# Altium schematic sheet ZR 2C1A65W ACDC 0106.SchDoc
size A3; SheetNumber: 2; SheetTotal: 2
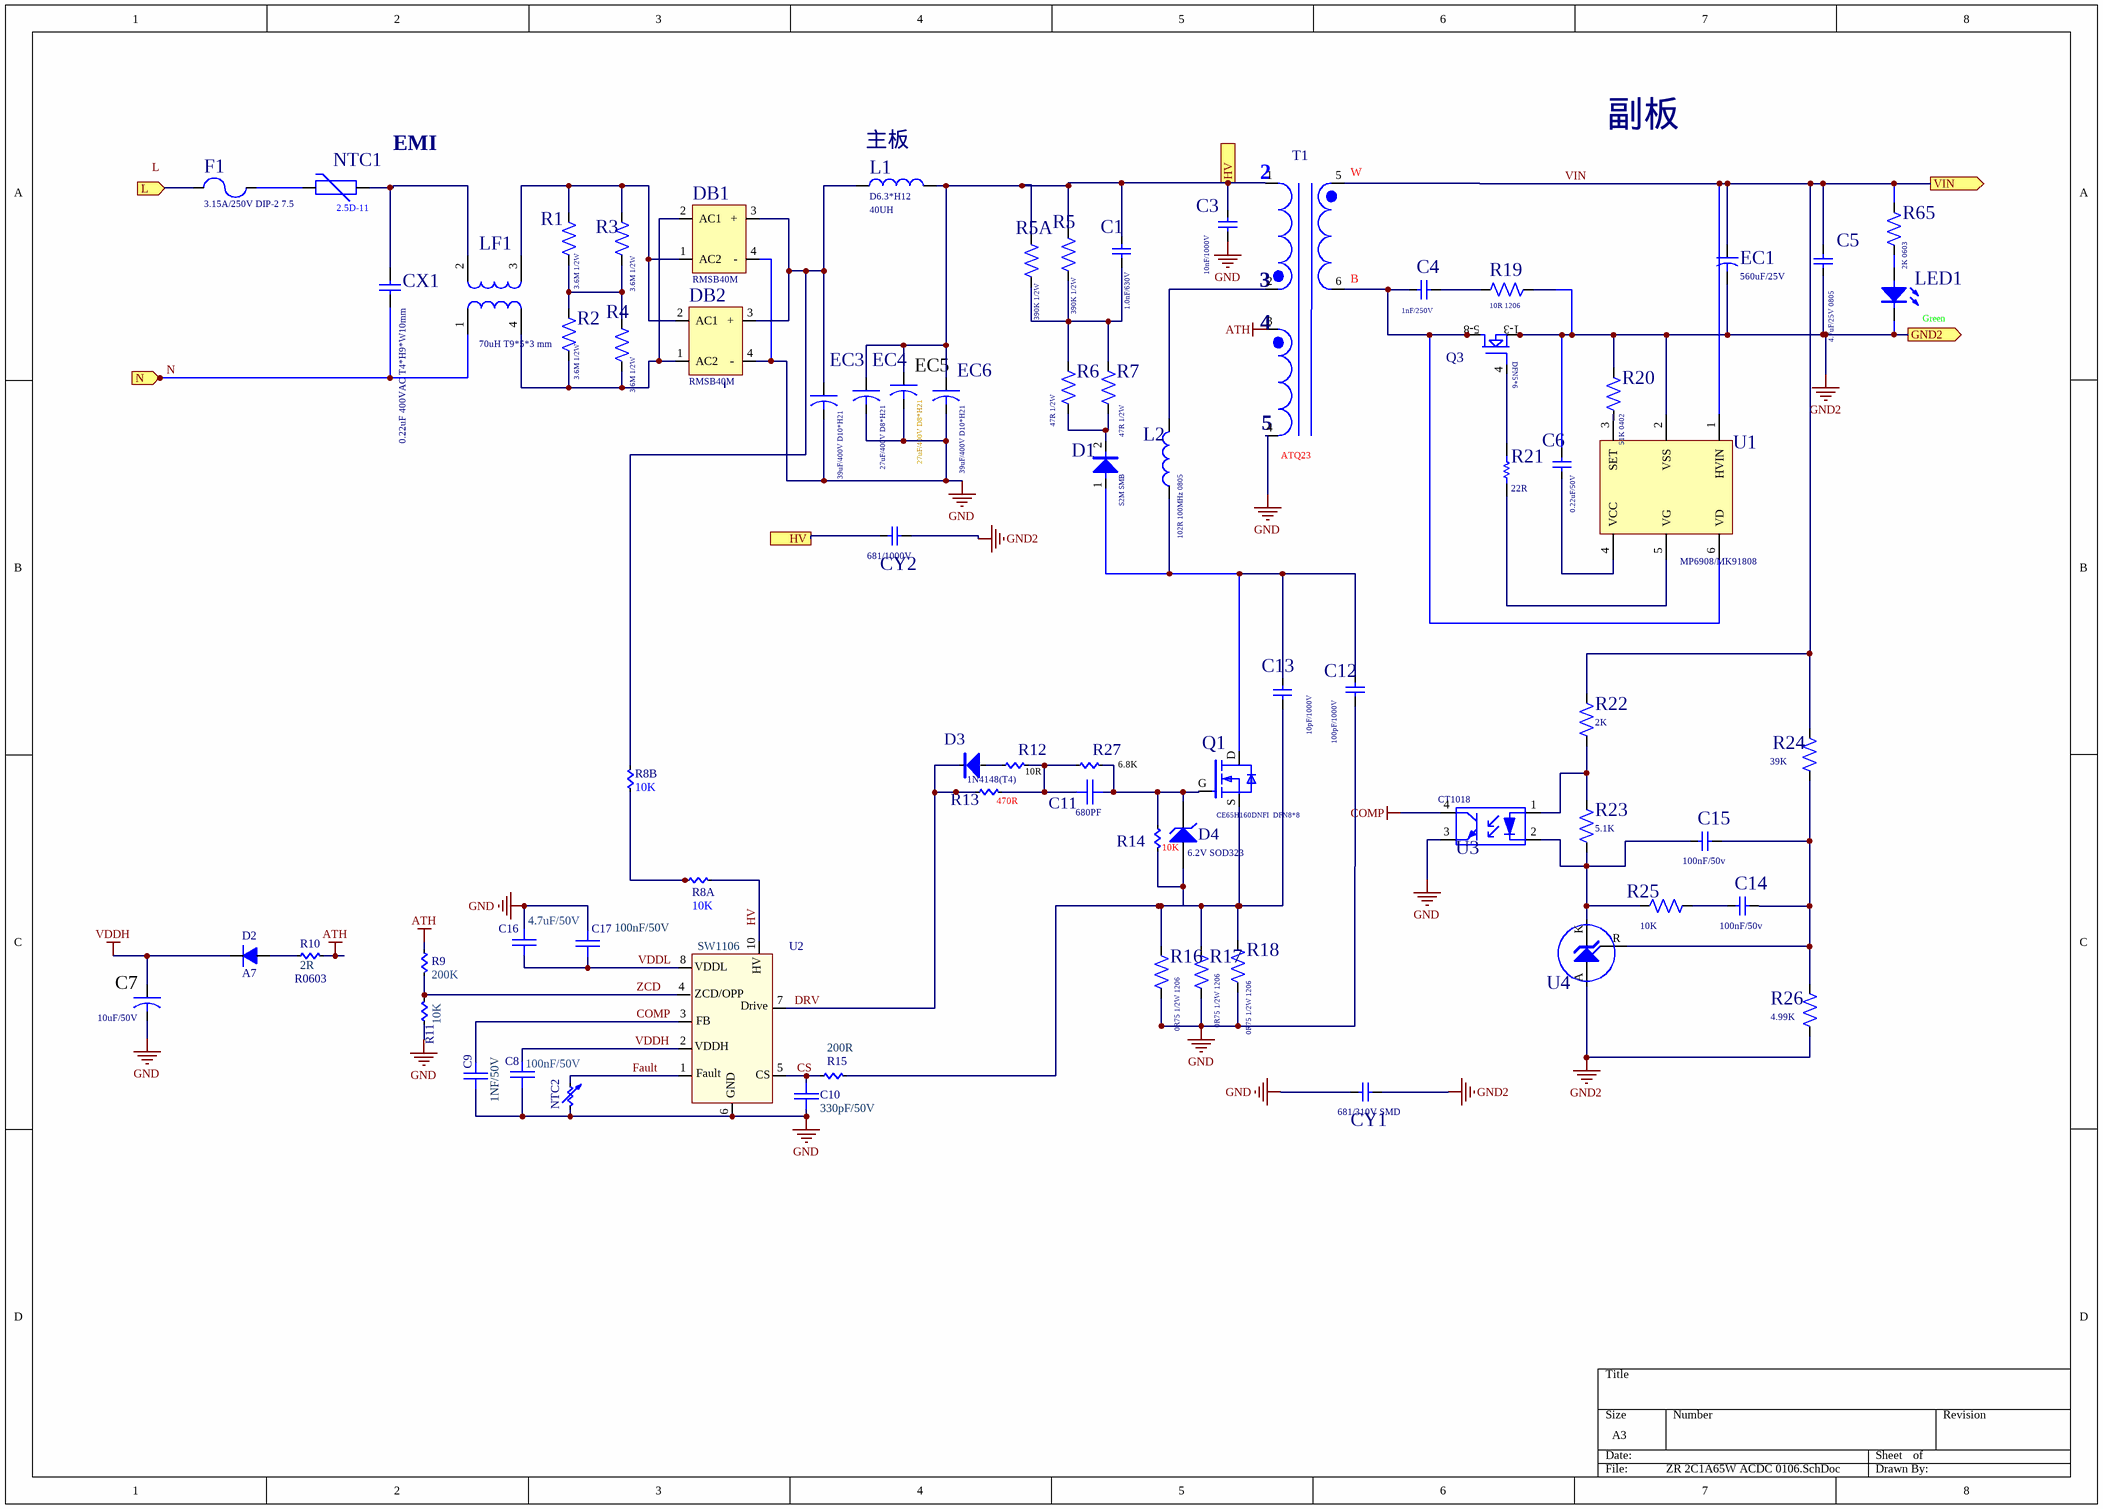
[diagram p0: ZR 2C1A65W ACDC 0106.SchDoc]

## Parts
C1  value 1.0nF/630V  [C1206]  (hidden comment: 10nF/500V)
C3  value 10nF/1000V  [1206C(H)]  (hidden comment: 10nF/500V)
C4  1nF/250V  [C0805]
C5  4.7uF/25V 0805  [C0805]
C6  0.22uF/50V  [C0603]
C7  10uF/50V  [Cap-8.5mm]
C8  100nF/50V  [1206C(H)]
C9  1NF/50V  [0603C(H)]
C10  330pF/50V  [0603C(H)]
C11  680PF  [0603C(H)]
C12  value 100pF/1000V  [C1206]  (hidden comment: 10nF/500V)
C13  value 10pF/1000V  [C1206]  (hidden comment: 10nF/500V)
C14  100nF/50v  [0603]
C15  100nF/50v  [0603]
C16  4.7uF/50V  [0603C(H)]
C17  100nF/50V  [0603C(H)]
CX1  0.22uF 400VAC T4*H9*W10mm  [XCAP_10*4  LISHI]
CY1  681/310V SMD  [CY-SMT]
CY2  681/1000V  [CY-SMT]
D1  S2M SMB  [SMA_F]
D2  A7  [SMD-(SOD-123)(H)]
D3  1N4148(T4)  [SMD-(SOD-323)(H)]
D4  6.2V SOD323  [SMD-(SOD-323)]
DB1  RMSB40M  [DBF310]
DB2  RMSB40M  [DBF310]
EC1  value 560uF/25V  [Cap  ( E )  6.5 * 8.0  Erect]  (hidden comment: E - Cap)
EC3  value 39uF/400V D10*H21  [Cap-10.5mm]  (hidden comment: 39uF/400V)
EC4  value 27uF/400V D8*H21  [Cap-8.5mm]  (hidden comment: 22uF/400V)
EC5  value 27uF/400V D8*H21  [Cap-8.5mm]  (hidden comment: 22uF/400V)
EC6  value 39uF/400V D10*H21  [Cap-10.5mm]  (hidden comment: 22uF/400V)
F1  3.15A/250V DIP-2 7.5  [F-9*4*8]
L1  D6.3*H12  value 40UH  [L12*6mm]
L2  value 102R 100MHz 0805  [0805]
LED1  Green  [LED-D5]
LF1  70uH T9*5*3 mm  [T9*5*3]
NTC1  2.5D-11  [5D-9]
NTC2  (no value)  [0603RH]
Q1  CE65H160DNFI  DFN8*8  [RUH4040M2/DFN3*3]
Q3  NMOS-8  [FQN5*6]  (value not drawn)
R1  3.6M 1/2W  [R1206]
R2  3.6M 1/2W  [R1206]
R3  3.6M 1/2W  [R1206]
R4  3.6M 1/2W  [R1206]
R5  390K 1/2W  [R1206]
R5A  390K 1/2W  [R1206]
R6  47R 1/2W  [R1206]
R7  47R 1/2W  [R1206]
R8A  10K  [1206RH]
R8B  10K  [1206RH]
R9  200K  [0603RH]
R10  2R  [1206RH]
R11  10K  [0603RH]
R12  10R  [0603RH]
R13  470R  [0603RH]
R14  10K  [0603RH]
R15  200R  [0603RH]
R16  0R75 1/2W 1206  [R1206]
R17  0R75 1/2W 1206  [R1206]
R18  0R75 1/2W 1206  [R1206]
R19  10R 1206  [R1206]
R20  51K 0402  [0603]
R21  value 22R  [0603]  (hidden comment: Res1)
R22  2K  [R0603]
R23  5.1K  [0603]
R24  39K  [0603]
R25  10K  [0603]
R26  4.99K  [0603]
R27  6.8K  [0603RH]
R65  2K 0603  [0603]
T1  ATQ23  [ATQ23.7]
U1  MP6908/MK91808  [IC-SOT-23-6P]
U2  SW1106  [NCP1342-SOIC-9]
U3  CT1018  [EL1018]
U4  (no value)  [SOT23-TL431]

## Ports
GND2 (out), HV, L (in), N (in), VIN (out)

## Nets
ATH: R9.2 R10.2
COMP: C9.1 U2.3(FB) U3.4(E)
GND: C3.2 C7.2 C8.2 C9.2 C10.2 C12.2 C16.1 C17.1 CY1.1 DB1.4(-) DB2.4(-) EC3.2 EC4.2 EC5.2 EC6.2 NTC2.2 R11.2 R16.1 R17.1 R18.1 T1.4 U2.6(GND) U3.3(C)
GND2: C5.1 C6.2 CY1.2 CY2.2 EC1.2 LED1.2(C) Q3.1(S) Q3.2(S) Q3.3(S) R19.1 R20.1 R26.1 U1.2(VSS) U4.A ; port GND2
VDDH: C7.1 C8.1 D2.2 U2.2(VDDH)
CS: C10.1 R15.2 U2.5(CS)
DRV: D3.K R13.2 U2.7(Drv)
Fault: NTC2.1 U2.1(Fault)
HV: C1.1 C3.1 CY2.1 EC4.1 EC5.1 EC6.1 L1.2 R5.2 R5A.2 T1.1 ; port HV
HV: R8A.1 U2.10(HV)  [a separate net that carries the same name]
L: F1.1 ; port L
N: CX1.1 LF1.1 ; port N
VDDL: C16.2 C17.2 U2.8(Vcc)
VIN: C5.2 EC1.1 R22.2 R24.2 R65.1 T1.5 ; port VIN
ZCD: R9.1 R11.1 U2.4(ZCD/OPP)
NetC1_2: C1.2 R5.1 R5A.1 R6.2 R7.2
NetC4_1: C4.1 Q3.5(D) Q3.6(D) Q3.7(D) Q3.8(D) Q3.9(D) T1.6 U1.6(VD)
NetC4_2: C4.2 R19.2
NetC6_1: C6.1 U1.4(VCC)
NetC11_1: C11.1 R12.1 R13.1 R27.2
NetC11_2: C11.2 D4.2(K) Q1.G R14.2 R27.1
NetC12_1: C12.1 C13.1 D1.1(A) L2.1 Q1.D
NetC13_2: C13.2 D4.1(A) Q1.S R14.1 R15.1 R16.2 R17.2 R18.2
NetC14_1: C14.1 R25.1
NetC14_2: C14.2 C15.2 R24.1 R26.2 U4.R
NetC15_1: C15.1 R23.1 R25.2 U3.2(K) U4.K
NetCX1_2: CX1.2 LF1.2 NTC1.2
NetD1_2: D1.2(K) R6.1 R7.1
NetD2_1: D2.1 R10.1
NetD3_A: D3.A R12.2
NetDB1_1: DB1.1(AC2) DB2.2(AC1) LF1.3 R1.2 R3.2
NetDB1_2: DB1.2(AC1) DB2.1(AC2) LF1.4 R2.1 R4.1
NetDB1_3: DB1.3(+) DB2.3(+) EC3.1 L1.1 R8B.1
NetF1_2: F1.2 NTC1.1
NetL2_2: L2.2 T1.2
NetLED1_1: LED1.1(A) R65.2
NetQ3_4: Q3.4(G) R21.2
NetR1_1: R1.1 R2.2 R3.1 R4.2
NetR8A_2: R8A.2 R8B.2
NetR20_2: R20.2 U1.3(SET)
NetR21_1: R21.1 U1.5(VG)
NetR22_1: R22.1 R23.2 U3.1(A)

Not connected (* = marked no-connect by the designer): T1 3; U1 1(HVIN)

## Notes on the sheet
- (near NTC1) EMI
- (near L1) 主板
- (near T1) 2
- (near T1) W
- 副板
- (near T1) 3
- (near T1) B
- (near T1) 4
- (near Q3) DFN5*6
- (near T1) 5
- Labels drawn without touching a wire or pin: ATH, L

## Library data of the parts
C1 C3-C6 C12-C15 CY1 CY2 = CAPACITOR
C7 EC3-EC6 = E-CAP
C8 = C0603: cap
C9 = CAP: 220pF/50V,X7R,±5%,0402
C10 = CAP: 100pF/50V,COG/NPO,±5%,0402
C11 = C0402: cap
C16 C17 = CAP: 10nF/50V,X7R,±10%,0402
CX1 = Cap: Capacitor; Value: 100pF
D1-D3 = DIODE
D4 = D Zener: Zener Diode
DB1 DB2 = BRIDGE2
EC1 = E - Cap: Electroytic Capacitor, 100uF/35V, ±20%, 105℃，Φ 6.5 * 12.0 mm
F1 = FUSE
L1 L2 = Inductor: Code_IEC: 1005
LED1 = LED
LF1 = LF
NTC1 = RT-NTC-SCH: PCB DECAL: RT-4X8.5-PCB
NTC2 = RES3: resistance
Q1 = MOS_E
R1-R5 R5A R6 R7 R16-R20 R22-R26 R65 = RESISTOR
R8A R8B = RES: 1K,±5%,1206
R9 = RES: 10K,±1% ,0603
R10 = RES: 2R,±5%,0603
R11 = RES: 4.3K,±1% ,0402
R12 R27 = RES: 2R,±1%,0402
R13 R14 = RES: resistance
R15 = RES: 1K,±1%,0402
R21 = Res1: Resistor
T1 = Transformer3
U1 = MK91808
U2 = NCP1342: NCP1342AMDCDAD1R2G，SOIC?9 NB，onsemi
U3 = OPTOISO
U4 = IC TL431: IC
